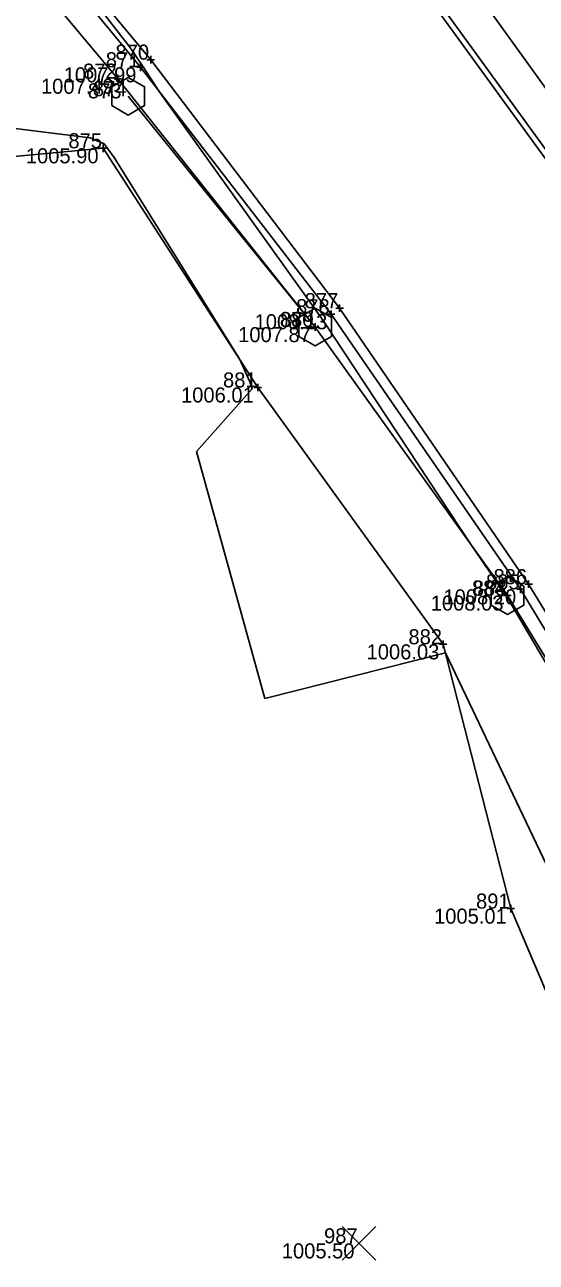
# Model space of a CAD drawing. Extents: x 2354693 to 2355622, y 637071 to 710080.
# Drawn here: x 2355257.5 to 2355298.3, y 709334.6 to 709433.1 of the extents above; entities that cross this region are included whole.
import ezdxf

# ---------------------------------------------------------------- set-up
doc = ezdxf.new("R2010")
doc.units = 0
for name, color, linetype in [('DT_X_Contour_Minor', 7, 'Continuous'), ('PM_X_Surveyed_Line', 7, 'Continuous'), ('PV_X_EOP', 7, 'Continuous'), ('PV_X_Shoulder', 7, 'Continuous'), ('RD_X_Cells', 7, 'Continuous'), ('RD_X_GR_Rt', 7, 'Continuous'), ('SV_X_Random_Point', 7, 'Continuous'), ('SV_X_Shot_Marker', 7, 'Continuous'), ('SV_X_Text_Elevation', 7, 'Continuous'), ('SV_X_Text_Name', 7, 'Continuous'), ('SV_X_Toe_of_Slope', 7, 'Continuous')]:
    doc.layers.add(name, color=color, linetype=linetype)

msp = doc.modelspace()

# ---------------------------------------------------------------- linework, layer by layer
at = {"layer": 'DT_X_Contour_Minor'}
for points in [[(2355306.586, 709369.523), (2355295.908, 709387.613), (2355295.68, 709387.93), (2355293.095, 709391.708), (2355281.293, 709409.573), (2355268.223, 709427.825), (2355266.878, 709429.868), (2355265.883, 709431.37), (2355234.817, 709471.309)], [(2355306.586, 709369.523), (2355295.908, 709387.613), (2355295.68, 709387.93), (2355293.095, 709391.708), (2355281.293, 709409.573), (2355268.223, 709427.825), (2355266.878, 709429.868), (2355265.883, 709431.37), (2355234.817, 709471.309)], [(2355299.903, 709364.535), (2355291.042, 709383.105), (2355276.638, 709379.475), (2355271.192, 709399.149), (2355275.631, 709404.134), (2355275.438, 709404.7), (2355274.643, 709406.468), (2355264.624, 709422.561), (2355263.813, 709423.668), (2355262.71, 709424.132), (2355250.914, 709425.611)], [(2355299.903, 709364.535), (2355291.042, 709383.105), (2355276.638, 709379.475), (2355271.192, 709399.149), (2355275.631, 709404.134), (2355275.438, 709404.7), (2355274.643, 709406.468), (2355264.624, 709422.561), (2355263.813, 709423.668), (2355262.71, 709424.132), (2355250.914, 709425.611)]]:
    msp.add_lwpolyline(points, dxfattribs=at)
at = {"layer": 'PM_X_Surveyed_Line'}
for points in [[(2355180.148, 709561.237), (2355214.753, 709522.888), (2355249.307, 709484.271), (2355284.017, 709443.142), (2355315.552, 709399.77), (2355328.888, 709377.573), (2355342.967, 709349.789), (2355353.365, 709324.191), (2355361.351, 709299.648), (2355367.764, 709272.473), (2355372.191, 709243.487), (2355373.87, 709217.884), (2355371.213, 709164.414), (2355367.135, 709139.625), (2355360.061, 709111.877), (2355351.618, 709085.78), (2355342.505, 709062.338), (2355329.445, 709031.419), (2355320.624, 709012.583)], [(2355165.86, 709547.265), (2355199.549, 709510.037), (2355233.994, 709470.593), (2355267.54, 709430.367), (2355282.605, 709410.565), (2355297.684, 709388.575), (2355309.404, 709369.446), (2355323.831, 709342.426), (2355334.056, 709318.38), (2355342.286, 709293.43), (2355348.466, 709267.168), (2355351.872, 709240.375), (2355352.964, 709217.38), (2355352.456, 709191.088), (2355350.186, 709167.624), (2355345.964, 709144.005), (2355339.847, 709117.861), (2355332.105, 709093.739), (2355322.597, 709069.077), (2355314.612, 709050.664), (2355300.362, 709021.696)]]:
    msp.add_lwpolyline(points, dxfattribs=at)
at = {"layer": 'PV_X_EOP'}
for points in [[(2355180.814, 709561.741), (2355215.64, 709523.556), (2355249.922, 709484.356), (2355284.407, 709443.36), (2355315.939, 709399.966), (2355329.751, 709378.355), (2355343.524, 709350.098), (2355349.219, 709351.4), (2355359.304, 709326.795), (2355367.588, 709301.754), (2355374.108, 709275.907), (2355368.17, 709272.694), (2355372.498, 709243.563), (2355374.502, 709217.665), (2355371.414, 709164.432), (2355367.842, 709139.325), (2355361.02, 709111.642), (2355352.388, 709085.56), (2355343.445, 709061.967), (2355330.49, 709031.083), (2355321.141, 709011.801)], [(2355165.324, 709546.951), (2355198.995, 709509.502), (2355233.405, 709470.111), (2355266.728, 709429.76), (2355281.934, 709410.085), (2355297.047, 709388.167), (2355308.637, 709369.042), (2355321.448, 709342.933), (2355321.339, 709342.62), (2355331.824, 709317.677), (2355340.036, 709292.971), (2355346.601, 709266.722), (2355349.963, 709239.902), (2355351.76, 709217.379), (2355351.561, 709190.756), (2355349.316, 709167.656), (2355345.615, 709144.125), (2355339.519, 709118.013), (2355331.95, 709093.674), (2355322.309, 709069.242), (2355314.268, 709051.111), (2355300.286, 709022.246)]]:
    msp.add_lwpolyline(points, dxfattribs=at)
at = {"layer": 'PV_X_Shoulder'}
for points in [[(2355182.191, 709563.218), (2355217.156, 709524.646), (2355251.587, 709486.128), (2355286.914, 709444.936), (2355318.238, 709401.514), (2355331.465, 709379.667), (2355345.367, 709350.943)], [(2355163.759, 709545.771), (2355197.773, 709507.918), (2355231.623, 709468.513), (2355264.913, 709428.851), (2355280.65, 709409.061), (2355295.988, 709387.673), (2355307.776, 709368.443), (2355321.17, 709342.601)]]:
    msp.add_lwpolyline(points, dxfattribs=at)
at = {"layer": 'RD_X_Cells'}
for points in [[(2355264.449, 709426.705), (2355265.748, 709425.955), (2355267.046, 709426.705), (2355267.046, 709428.205), (2355265.748, 709428.955), (2355264.449, 709428.205), (2355264.449, 709426.705)], [(2355279.35, 709408.315), (2355280.648, 709407.565), (2355281.946, 709408.315), (2355281.946, 709409.815), (2355280.648, 709410.565), (2355279.35, 709409.815), (2355279.35, 709408.315)], [(2355294.693, 709386.914), (2355295.991, 709386.164), (2355297.29, 709386.914), (2355297.29, 709388.414), (2355295.991, 709389.164), (2355294.693, 709388.414), (2355294.693, 709386.914)]]:
    msp.add_lwpolyline(points, dxfattribs=at)
at = {"layer": 'RD_X_GR_Rt'}
msp.add_lwpolyline([(2355265.748, 709427.455), (2355280.648, 709409.065), (2355295.991, 709387.664), (2355307.776, 709368.443), (2355321.605, 709341.331)], dxfattribs=at)
at = {"layer": 'SV_X_Random_Point'}
for p, q in [((2355282.82, 709334.723), (2355285.487, 709337.393)), ((2355282.82, 709337.393), (2355285.487, 709334.723))]:
    msp.add_line(p, q, dxfattribs=at)
at = {"layer": 'SV_X_Shot_Marker'}
for p, q in [((2355267.84, 709430.367), (2355267.24, 709430.367)), ((2355267.54, 709430.667), (2355267.54, 709430.067)), ((2355264.913, 709429.151), (2355264.913, 709428.551)), ((2355267.028, 709429.76), (2355266.428, 709429.76)), ((2355266.728, 709430.06), (2355266.728, 709429.46)), ((2355265.213, 709428.851), (2355264.613, 709428.851)), ((2355264.037, 709423.308), (2355263.437, 709423.308)), ((2355263.737, 709423.608), (2355263.737, 709423.008)), ((2355281.934, 709410.385), (2355281.934, 709409.785)), ((2355282.905, 709410.565), (2355282.305, 709410.565)), ((2355282.605, 709410.865), (2355282.605, 709410.265)), ((2355282.234, 709410.085), (2355281.634, 709410.085)), ((2355280.95, 709409.061), (2355280.35, 709409.061)), ((2355280.65, 709409.361), (2355280.65, 709408.761)), ((2355276.079, 709404.551), (2355276.079, 709403.951)), ((2355276.379, 709404.251), (2355275.779, 709404.251)), ((2355297.684, 709388.875), (2355297.684, 709388.275)), ((2355295.988, 709387.973), (2355295.988, 709387.373)), ((2355297.347, 709388.167), (2355296.747, 709388.167)), ((2355297.047, 709388.467), (2355297.047, 709387.867)), ((2355297.984, 709388.575), (2355297.384, 709388.575)), ((2355296.288, 709387.673), (2355295.688, 709387.673)), ((2355291.167, 709383.787), (2355290.568, 709383.787)), ((2355290.868, 709384.087), (2355290.868, 709383.487)), ((2355296.561, 709362.728), (2355295.961, 709362.728)), ((2355296.261, 709363.028), (2355296.261, 709362.428))]:
    msp.add_line(p, q, dxfattribs=at)
at = {"layer": 'SV_X_Toe_of_Slope'}
msp.add_lwpolyline([(2355160.054, 709542.815), (2355193.589, 709505.752), (2355228.581, 709465.865), (2355241.119, 709447.492), (2355241.223, 709431.104), (2355250.635, 709422.105), (2355263.737, 709423.308), (2355276.079, 709404.251), (2355290.868, 709383.787), (2355296.261, 709362.728), (2355304.651, 709343.066)], dxfattribs=at)

# ---------------------------------------------------------------- texts
at = {"layer": 'SV_X_Text_Elevation'}
for s, p in [('1007.99', (2355260.599, 709428.56)), ('1007.49', (2355258.784, 709427.651)), ('1005.90', (2355257.578, 709422.108)), ('1008.13', (2355275.825, 709408.885)), ('1007.87', (2355274.513, 709407.861)), ('1006.01', (2355269.957, 709403.051)), ('1008.03', (2355289.878, 709386.473)), ('1008.20', (2355290.888, 709386.967)), ('1006.03', (2355284.758, 709382.587)), ('1005.01', (2355290.139, 709361.528)), ('1005.50', (2355277.995, 709334.858))]:
    msp.add_text(s, height=1.2, dxfattribs=at).set_placement(p)
at = {"layer": 'SV_X_Text_Name'}
for s, p in [('870', (2355264.732, 709430.367)), ('871', (2355263.957, 709429.76)), ('872', (2355262.144, 709428.851)), ('873', (2355262.527, 709427.282)), ('874', (2355262.929, 709427.455)), ('875', (2355260.974, 709423.308)), ('877', (2355279.818, 709410.565)), ('878', (2355279.138, 709410.085)), ('880', (2355277.84, 709409.065)), ('879', (2355277.873, 709409.061)), ('881', (2355273.308, 709404.251)), ('886', (2355294.885, 709388.575)), ('884', (2355293.169, 709387.673)), ('883', (2355293.233, 709387.664)), ('885', (2355294.284, 709388.167)), ('882', (2355288.099, 709383.787)), ('891', (2355293.49, 709362.728)), ('987', (2355281.367, 709336.058))]:
    msp.add_text(s, height=1.2, dxfattribs=at).set_placement(p)

doc.saveas('drawing.dxf')
